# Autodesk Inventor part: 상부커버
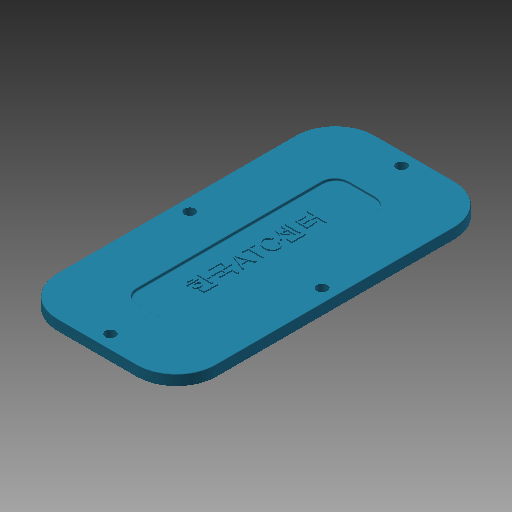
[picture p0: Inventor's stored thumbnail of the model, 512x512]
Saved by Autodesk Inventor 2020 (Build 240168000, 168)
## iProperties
Created: 2016-02
Part Number: 상부커버
Material: 강철, 연강
Document SubType Name: Modeling
Designer: mduedu
Density: 1 g/cm^3
Mass: 15.5198 g
Surface Area: 149.263 cm^2
Volume: 15.5198 cm^3
Appearance: 터키옥색
Author: mduedu
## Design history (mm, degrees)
sketch "스케치1"
  geometry: L1 (30, 60)-(-30, 60); L2 (-30, 60)-(-30, -60); L3 (-30, -60)-(30, -60); L4 (30, -60)-(30, 60); L5 (30, 60)-(-30, -60); L6 (-30, 60)-(30, -60); 1 further point
  constraints: 12 end point, 2 midpoint, 2 parallel, 1 horizontal, 1 perpendicular
  dimensions: "d0" = 60 distance of L2.end L3.end; "d2" = 120 distance of L1.end L2.end
extrude "돌출1" new body sketch "스케치1" distance "d3" = 4; taper "d4" = 0 deg
fillet "모깎기1" dims "d5" = 15
sketch "스케치2"
  geometry: L1 (30, 45)-(30, -45) reference; L2 (15, -60)-(-15, -60) reference; L3 (-30, -45)-(-30, 45) reference; L4 (-15, 60)-(15, 60) reference; L5 (25, 45)-(25, -45); L6 (15, -55)-(-15, -55); L7 (-25, -45)-(-25, 45); L8 (-15, 55)-(15, 55); A1 r 15 centre (15, 45) between (30, 45) and (15, 60) reference; A2 r 15 centre (15, -45) between (15, -60) and (30, -45) reference; A3 r 15 centre (-15, -45) between (-30, -45) and (-15, -60) reference; A4 r 15 centre (-15, 45) between (-15, 60) and (-30, 45) reference; A5 r 10 centre (15, 45) between (25, 45) and (15, 55); A6 r 10 centre (15, -45) between (15, -55) and (25, -45); A7 r 10 centre (-15, -45) between (-25, -45) and (-15, -55); A8 r 10 centre (-15, 45) between (-15, 55) and (-25, 45); 4 further points
  constraints: 8 end point, 8 point on circle, 4 centre point, 4 midpoint, 7 other
  dimensions: "d8" = 5 distance between parallel lines of L7 L3
hole "구멍1" sketch "스케치2" at (0, 55), (25, 0), (0, -55), (-25, 0) diameter "d9" = 4; stored, may be unused: countersink angle "d13" = 90 deg, drill point angle "d15" = 118 deg; dims "d10" = 6, "d11" = 4, "d12" = 2, "d14" = 8
sketch "스케치3"
  geometry: L1 (10, -40)-(-10, -40); L2 (-10, -40)-(-10, 40); L3 (-10, 40)-(10, 40); L4 (10, 40)-(10, -40); L5 (10, -40)-(-10, 40); L6 (-10, -40)-(10, 40); 1 further point
  constraints: 12 end point, 2 equal length, 2 midpoint, 1 horizontal, 1 parallel
  dimensions: "d16" = 80 distance of L1.end L2.end; "d18" = 20 distance of L2.end L3.end
extrude "돌출2" cut sketch "스케치3" distance "d19" = 1; taper "d20" = 0 deg
fillet "모깎기2" dims "d21" = 5
fillet "모깎기3" dims "d22" = 0.3
fillet "모깎기4" dims "d23" = 0.3
sketch "스케치4"
  geometry: 2 further points
  constraints: 1 coincident, 1 other
feature "엠보싱1" sketch "스케치4" dims "d0" = 60, "d2" = 120, "d11" = 4, "d24" = 0.5, "d25" = 0
node "솔리드1"
node "절단 모서리 투영1"
